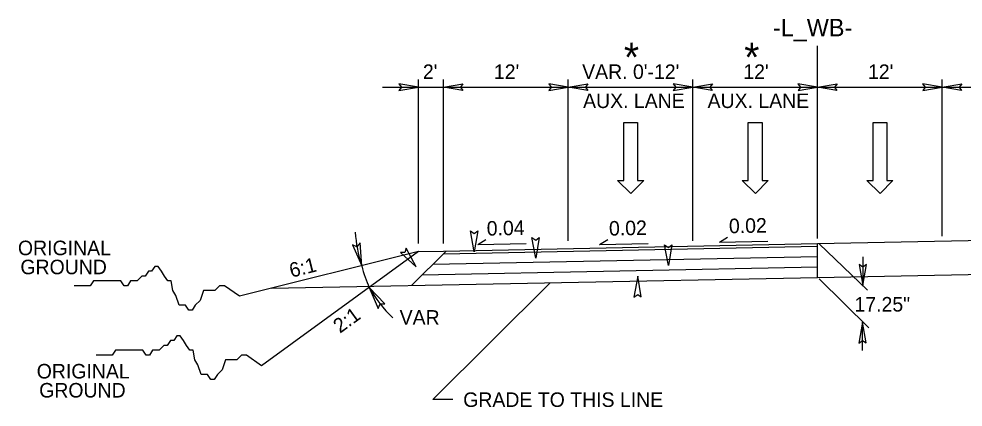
# Model space of a CAD drawing. Extents: x 1726582 to 1728895, y 538986 to 541550.
# Drawn here: x 1726942.3 to 1727397, y 540345.9 to 540533.1 of the extents above; entities that cross this region are included whole.
import ezdxf

# ---------------------------------------------------------------- set-up
doc = ezdxf.new("R2010")
doc.units = 0
for name, color, linetype in [('Default', 7, 'Continuous'), ('GSExisting', 7, 'Continuous'), ('GSProposed', 7, 'Continuous'), ('GSRelocate', 7, 'Continuous'), ('GSRemove', 7, 'Continuous'), ('GSReplace', 7, 'Continuous'), ('Typical Terminator CELL', 7, 'Continuous'), ('Typical Text General CELL', 7, 'Continuous')]:
    doc.layers.add(name, color=color, linetype=linetype)

msp = doc.modelspace()

# ---------------------------------------------------------------- linework, layer by layer
at = {"layer": 'Default'}
for p, q in [((1727326.84, 540427.18), (1727326.84, 540520.09)), ((1727134.69, 540424.78), (1727134.69, 540503.77)), ((1727146.69, 540424.78), (1727146.69, 540503.77)), ((1727146.69, 540424.78), (1727146.69, 540502.57)), ((1727206.85, 540425.98), (1727206.85, 540503.77)), ((1727266.79, 540425.98), (1727266.79, 540503.77)), ((1727326.84, 540427.18), (1727326.84, 540503.77)), ((1727386.88, 540428.38), (1727386.88, 540503.77)), ((1727117.43, 540500.07), (1727146.8, 540500.07)), ((1727146.8, 540500.07), (1727206.85, 540500.07)), ((1727206.96, 540500.07), (1727267.01, 540500.07)), ((1727266.9, 540500.07), (1727326.94, 540500.07)), ((1727326.94, 540500.07), (1727386.99, 540500.07)), ((1727386.99, 540500.07), (1727447.04, 540500.07)), ((1727233.58, 540455.17), (1727233.58, 540483.17)), ((1727233.58, 540483.17), (1727240.18, 540483.17)), ((1727240.18, 540483.17), (1727240.18, 540455.17)), ((1727293.52, 540455.17), (1727293.52, 540483.17)), ((1727293.52, 540483.17), (1727300.12, 540483.17)), ((1727300.12, 540483.17), (1727300.12, 540455.17)), ((1727353.57, 540455.17), (1727353.57, 540483.17)), ((1727353.57, 540483.17), (1727360.17, 540483.17)), ((1727360.17, 540483.17), (1727360.17, 540455.17)), ((1727236.98, 540448.87), (1727230.58, 540455.17)), ((1727230.58, 540455.17), (1727233.58, 540455.17)), ((1727243.18, 540455.17), (1727236.98, 540448.87)), ((1727240.18, 540455.17), (1727243.18, 540455.17)), ((1727296.92, 540448.87), (1727290.52, 540455.17)), ((1727290.52, 540455.17), (1727293.52, 540455.17)), ((1727303.12, 540455.17), (1727296.92, 540448.87)), ((1727300.12, 540455.17), (1727303.12, 540455.17)), ((1727356.97, 540448.87), (1727350.57, 540455.17)), ((1727350.57, 540455.17), (1727353.57, 540455.17)), ((1727363.17, 540455.17), (1727356.97, 540448.87)), ((1727360.17, 540455.17), (1727363.17, 540455.17)), ((1727327.66, 540424.6), (1727350.96, 540402.3)), ((1727348.61, 540418.3), (1727348.61, 540404.54)), ((1727327.66, 540407.66), (1727351.49, 540384.17)), ((1727348.49, 540373.13), (1727348.49, 540386.89))]:
    msp.add_line(p, q, dxfattribs=at)
for points in [[(1727125.31, 540498.46), (1727134.69, 540500.07), (1727125.25, 540501.74), (1727126.45, 540500.07)], [(1727156.07, 540498.46), (1727146.69, 540500.07), (1727156.13, 540501.74), (1727154.93, 540500.07)], [(1727197.47, 540498.46), (1727206.85, 540500.07), (1727197.42, 540501.74), (1727198.62, 540500.07)], [(1727216.23, 540498.46), (1727206.85, 540500.07), (1727216.28, 540501.74), (1727215.08, 540500.07)], [(1727257.41, 540498.46), (1727266.79, 540500.07), (1727257.36, 540501.74), (1727258.56, 540500.07)], [(1727276.17, 540498.46), (1727266.79, 540500.07), (1727276.22, 540501.74), (1727275.02, 540500.07)], [(1727317.46, 540498.46), (1727326.84, 540500.07), (1727317.41, 540501.74), (1727318.6, 540500.07)], [(1727336.21, 540498.46), (1727326.84, 540500.07), (1727336.27, 540501.74), (1727335.07, 540500.07)], [(1727377.51, 540498.46), (1727386.88, 540500.07), (1727377.45, 540501.74), (1727378.65, 540500.07)], [(1727396.26, 540498.46), (1727386.88, 540500.07), (1727396.31, 540501.74), (1727395.12, 540500.07)], [(1727102.93, 540424.07), (1727107.38, 540414.04), (1727106.58, 540425.05), (1727105.06, 540423.24)], [(1727118.47, 540395.62), (1727110.94, 540403.59), (1727115.35, 540393.48), (1727116.19, 540395.69)], [(1727118.47, 540395.62), (1727110.94, 540403.59), (1727115.35, 540393.48), (1727116.19, 540395.69)]]:
    msp.add_lwpolyline(points, close=True, dxfattribs=at)
at = {"layer": 'GSExisting'}
for points in [[(1727048.47, 540399.31), (1727041.25, 540404.38), (1727038.91, 540404.38), (1727036.58, 540402.05), (1727035.02, 540402.05), (1727032.68, 540402.05), (1727031.13, 540402.05), (1727029.57, 540397.36), (1727027.23, 540395.04), (1727025.67, 540392.69), (1727024.11, 540392.69), (1727022.56, 540395.04), (1727021, 540395.04), (1727019.44, 540395.04), (1727017.89, 540399.71), (1727016.33, 540402.05), (1727015.55, 540406.73), (1727013.99, 540406.73), (1727012.43, 540409.05), (1727010.88, 540411.4), (1727009.32, 540413.74), (1727007.76, 540413.74), (1727006.2, 540411.4), (1727004.65, 540411.4), (1727003.09, 540409.05), (1727001.53, 540409.05), (1726999.19, 540406.73), (1726997.64, 540406.73), (1726996.08, 540406.73), (1726994.52, 540404.38), (1726992.96, 540404.38), (1726991.41, 540406.73), (1726989.85, 540406.73), (1726988.29, 540406.73), (1726986.74, 540406.73), (1726985.18, 540406.73), (1726982.84, 540406.73), (1726980.51, 540406.73), (1726978.17, 540406.73), (1726976.61, 540404.38), (1726974.28, 540404.38), (1726971.94, 540404.38), (1726968.82, 540404.38)], [(1727059.08, 540365.87), (1727051.86, 540370.94), (1727049.52, 540370.94), (1727047.19, 540368.61), (1727045.63, 540368.61), (1727043.29, 540368.61), (1727041.73, 540368.61), (1727040.18, 540363.92), (1727037.84, 540361.6), (1727036.28, 540359.25), (1727034.72, 540359.25), (1727033.17, 540361.6), (1727031.61, 540361.6), (1727030.05, 540361.6), (1727028.49, 540366.27), (1727026.94, 540368.61), (1727026.15, 540373.29), (1727024.6, 540373.29), (1727023.04, 540375.61), (1727021.48, 540377.96), (1727019.93, 540380.3), (1727018.37, 540380.3), (1727016.81, 540377.96), (1727015.25, 540377.96), (1727013.7, 540375.61), (1727012.14, 540375.61), (1727009.8, 540373.29), (1727008.24, 540373.29), (1727006.69, 540373.29), (1727005.13, 540370.94), (1727003.57, 540370.94), (1727002.01, 540373.29), (1727000.46, 540373.29), (1726998.9, 540373.29), (1726997.34, 540373.29), (1726995.79, 540373.29), (1726993.45, 540373.29), (1726991.11, 540373.29), (1726988.77, 540373.29), (1726987.22, 540370.94), (1726984.89, 540370.94), (1726982.55, 540370.94), (1726979.43, 540370.94)]]:
    msp.add_lwpolyline(points, dxfattribs=at)
for centre, start, end in [((1727164.55, 540433.38), 182.9343, 198.686), ((1727163.68, 540432.93), 209.0778, 226.6941), ((1727163.68, 540432.93), 209.0778, 226.6941)]:
    msp.add_arc(centre, 60.35, start, end, dxfattribs=at)
msp.add_ellipse((1727136.27, 540448.47), major_axis=(-9.27, -59.64), ratio=0.5, start_param=5.403228, end_param=5.638322, dxfattribs=at)
at = {"layer": 'GSProposed'}
for p, q in [((1727163.21, 540424.28), (1727167.13, 540426.65)), ((1727163.21, 540424.28), (1727186.52, 540424.75)), ((1727221.91, 540424.28), (1727225.82, 540426.65)), ((1727221.91, 540424.28), (1727245.22, 540424.75)), ((1727279.67, 540425.43), (1727283.58, 540427.8)), ((1727279.67, 540425.43), (1727302.98, 540425.9))]:
    msp.add_line(p, q, dxfattribs=at)
at = {"layer": 'GSReplace'}
for p, q in [((1727326.84, 540424.71), (1727561.06, 540429.4)), ((1727146.69, 540421.11), (1727326.81, 540424.71)), ((1727326.84, 540408.45), (1727326.84, 540424.71)), ((1727134.69, 540420.87), (1727048.47, 540399.31)), ((1727134.69, 540420.87), (1727059.08, 540365.87)), ((1727147.97, 540421.13), (1727131.38, 540404.54)), ((1727134.69, 540420.87), (1727146.69, 540421.11)), ((1727146.69, 540419.86), (1727326.84, 540423.46)), ((1727141.59, 540414.75), (1727326.84, 540418.46)), ((1727136.48, 540409.65), (1727326.84, 540413.45)), ((1727326.84, 540408.45), (1727561.09, 540413.13)), ((1727063.98, 540403.19), (1727326.84, 540408.45))]:
    msp.add_line(p, q, dxfattribs=at)
at = {"layer": 'Typical Terminator CELL'}
for p, q in [((1727141.67, 540349.49), (1727198.13, 540405.87)), ((1727151.23, 540349.49), (1727141.67, 540349.49))]:
    msp.add_line(p, q, dxfattribs=at)
for points in [[(1727163.25, 540430.8), (1727161.52, 540420.75), (1727159.73, 540430.86), (1727161.52, 540429.57)], [(1727192.87, 540427.67), (1727191.14, 540417.63), (1727189.35, 540427.73), (1727191.14, 540426.45)], [(1727256.74, 540424.13), (1727255.01, 540414.09), (1727253.23, 540424.19), (1727255.01, 540422.9)], [(1727126.08, 540420.39), (1727133.59, 540413.5), (1727128.83, 540422.59), (1727128.2, 540420.48)], [(1727346.88, 540414.59), (1727348.61, 540404.54), (1727350.4, 540414.65), (1727348.61, 540413.36)], [(1727241.98, 540399), (1727240.25, 540409.05), (1727238.46, 540398.95), (1727240.25, 540400.23)], [(1727350.22, 540376.85), (1727348.49, 540386.89), (1727346.71, 540376.79), (1727348.49, 540378.07)]]:
    msp.add_lwpolyline(points, close=True, dxfattribs=at)

# ---------------------------------------------------------------- texts
at = {"layer": 'Default'}
msp.add_text('17.25"', height=7.005, dxfattribs=at).set_placement((1727344.65, 540391.97))
at = {"layer": 'GSProposed'}
for s, height, p in [('*', 14.01, (1727233.63, 540507.58)), ('*', 14.01, (1727291.57, 540507.58)), ("2'", 7.005, (1727136.81, 540504.08)), ("12'", 7.005, (1727171.01, 540504.08)), ("VAR. 0'-12'", 7.0055, (1727213.51, 540504.08)), ("12'", 7.005, (1727291.11, 540504.08)), ("12'", 7.005, (1727351.16, 540504.08)), ('AUX. LANE', 7.005, (1727213.96, 540490.06)), ('AUX. LANE', 7.005, (1727273.9, 540490.06))]:
    msp.add_text(s, height=height, dxfattribs=at).set_placement(p)
for s, p in [('0.04', (1727167.62, 540428.54)), ('0.02', (1727226.5, 540428.55)), ('0.02', (1727284.26, 540429.7))]:
    msp.add_text(s, height=7.005, rotation=1.1457, dxfattribs=at).set_placement(p)
at = {"layer": 'GSRelocate'}
for s, p in [('ORIGINAL', (1726941.82, 540419.13)), ('GROUND', (1726943, 540409.95)), ('VAR', (1727125.62, 540385.63)), ('ORIGINAL', (1726950.86, 540359.7)), ('GROUND', (1726952.04, 540350.52))]:
    msp.add_text(s, height=7.005, dxfattribs=at).set_placement(p)
for s, rotation, p in [('6:1', 14.0362, (1727073.49, 540408.25)), ('2:1', 36.0298, (1727096.88, 540381.21))]:
    msp.add_text(s, height=7.005, rotation=rotation, dxfattribs=at).set_placement(p)
at = {"layer": 'GSRemove'}
msp.add_text('-L_WB-', height=8.421, dxfattribs=at).set_placement((1727305.41, 540524.63))
at = {"layer": 'Typical Text General CELL'}
msp.add_text('GRADE TO THIS LINE', height=7.0055, rotation=360, dxfattribs=at).set_placement((1727156.23, 540345.98))

doc.saveas('drawing.dxf')
